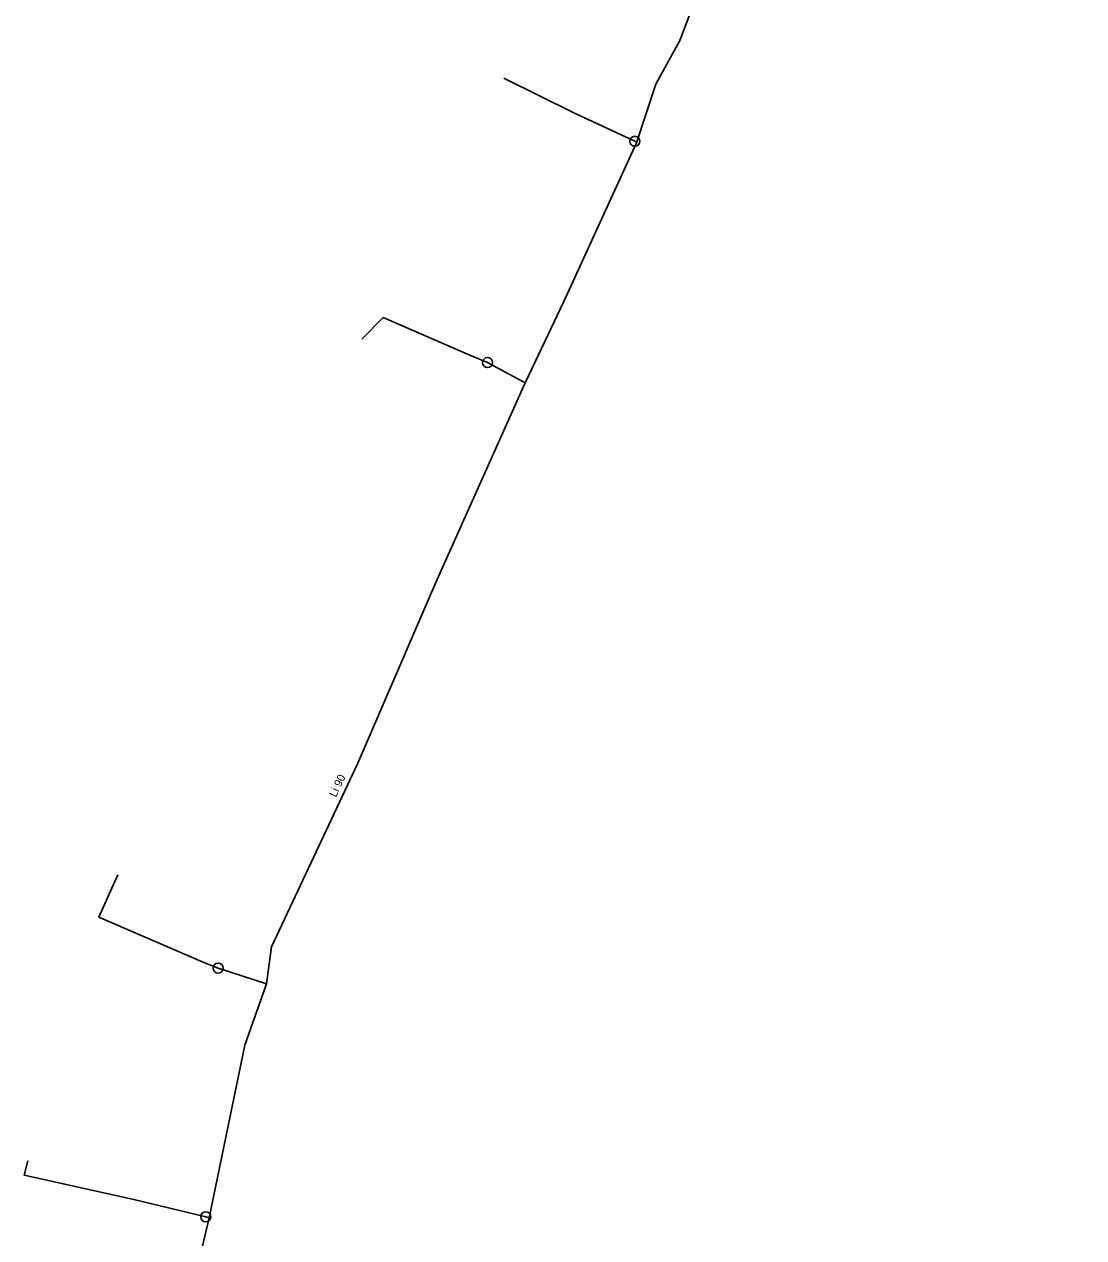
# Model space of a CAD drawing. Extents: x -684835 to -684548, y -1163297 to -1162881.
# Drawn here: x -684737.5 to -684684.6, y -1163147.7 to -1163087.1 of the extents above; entities that cross this region are included whole.
import ezdxf

# ---------------------------------------------------------------- set-up
doc = ezdxf.new("R2010")
doc.units = 0
for name, color, linetype in [('Popis vodovodních řadů', 7, 'Continuous'), ('Vod přípojky-voda pitná', 7, 'Continuous'), ('Vodovodní řad', 7, 'Continuous'), ('Vodovodní šoupata', 7, 'Continuous')]:
    doc.layers.add(name, color=color, linetype=linetype)

msp = doc.modelspace()

# ---------------------------------------------------------------- linework, layer by layer
at = {"layer": 'Vod přípojky-voda pitná'}
for points in [[(-684710.05, -1163091.51), (-684713.58, -1163089.76)], [(-684710.05, -1163091.51), (-684707.03, -1163092.91), (-684706.95, -1163092.99)], [(-684715.28, -1163103.6), (-684719.6, -1163101.72), (-684720.68, -1163102.8)], [(-684712.51, -1163104.98), (-684714.39, -1163103.97), (-684715.28, -1163103.6)], [(-684728.56, -1163133.95), (-684733.81, -1163131.68), (-684732.87, -1163129.56)], [(-684725.44, -1163135.01), (-684727.85, -1163134.23), (-684728.56, -1163133.95)], [(-684732.07, -1163145.8), (-684737.54, -1163144.58), (-684737.36, -1163143.86)], [(-684728.3, -1163146.71), (-684728.47, -1163146.66), (-684732.07, -1163145.8)]]:
    msp.add_lwpolyline(points, dxfattribs=at)
at = {"layer": 'Vodovodní řad'}
for points in [[(-684684.6, -1163040.18), (-684685.72, -1163043.02), (-684686.62, -1163045.29), (-684688.25, -1163050.21), (-684691.38, -1163057.36), (-684693.43, -1163061.72), (-684696.97, -1163069.02), (-684701.39, -1163079.1), (-684702.15, -1163080.49), (-684702.53, -1163081.93), (-684704.79, -1163087.87), (-684705.98, -1163090.06)], [(-684705.98, -1163090.06), (-684706.95, -1163092.99), (-684710.58, -1163100.92), (-684712.51, -1163104.98), (-684716.99, -1163114.99), (-684720.87, -1163123.98), (-684725.19, -1163133.16), (-684725.44, -1163135.01), (-684726.52, -1163138.08), (-684728.3, -1163146.71), (-684730.36, -1163155.46), (-684731.69, -1163160.97), (-684731.63, -1163163.37)]]:
    msp.add_lwpolyline(points, dxfattribs=at)
at = {"layer": 'Vodovodní šoupata'}
for centre in [(-684707.03, -1163092.91), (-684714.39, -1163103.97), (-684727.85, -1163134.23), (-684728.47, -1163146.66)]:
    msp.add_circle(centre, 0.25, dxfattribs=at)

# ---------------------------------------------------------------- texts
at = {"layer": 'Popis vodovodních řadů'}
msp.add_text('Li 90', height=0.4, rotation=64.79888, dxfattribs=at).set_placement((-684721.964, -1163125.717))

doc.saveas('drawing.dxf')
